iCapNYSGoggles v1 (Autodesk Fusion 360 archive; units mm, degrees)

design "iCapNYSGoggles" references "iCapGoggles_led_eyeCover"
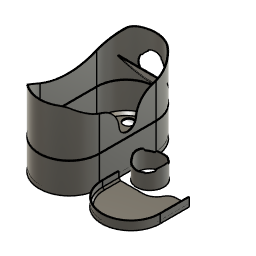
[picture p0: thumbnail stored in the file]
component_insert "コンポーネントの挿入"
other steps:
create_component "CreateComponent1"

design "iCapGoggles_led_eyeCover"
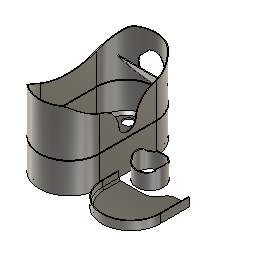
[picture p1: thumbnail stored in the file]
